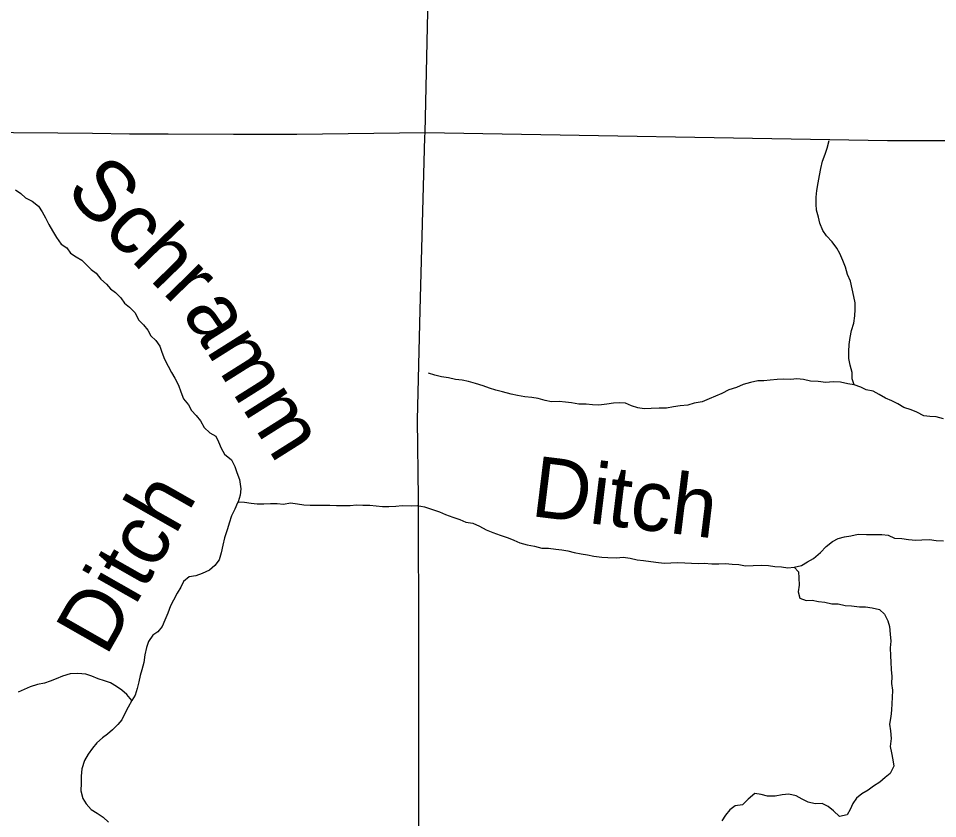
# Model space of a CAD drawing. Extents: x 1857828 to 2277390, y 930619 to 1324581.
# Drawn here: x 2048680 to 2056259, y 1210395 to 1216995 of the extents above; entities that cross this region are included whole.
import ezdxf

# ---------------------------------------------------------------- set-up
doc = ezdxf.new("R2010")
doc.units = 0
for name, color, linetype in [('GM_X_County_Road', 7, 'Continuous'), ('GM_X_Minor_River', 7, 'Continuous'), ('GM_X_Minor_River_Text', 7, 'Continuous')]:
    doc.layers.add(name, color=color, linetype=linetype)

msp = doc.modelspace()

# ---------------------------------------------------------------- linework, layer by layer
at = {"layer": 'GM_X_County_Road'}
for points in [[(2052033.4, 1216053.9), (2052081.4, 1218170.7), (2052124.1, 1220530.3), (2052126.8, 1220631.7), (2052134.8, 1220709.1), (2052153.5, 1220767.9), (2052228.2, 1220904), (2052543.2, 1221491.3), (2052548.6, 1221659.4), (2052615.3, 1223968.4), (2052658, 1225343), (2052682, 1226907.2)], [(2046506.2, 1216127.5), (2048640.4, 1216054.1), (2049006, 1216051.1), (2049291.8, 1216047.4), (2049597.6, 1216044), (2049915.3, 1216042.6), (2050452.9, 1216041), (2050976.4, 1216041.3), (2052033.4, 1216053.9), (2055846.4, 1215989.3), (2056807.6, 1215987.2), (2057087.8, 1215986.6), (2059001.3, 1216013.3), (2059118.3, 1216013.3), (2059283.5, 1216005.2), (2059444.8, 1215973), (2060293.5, 1215682.6), (2060318.6, 1215682.6)], [(2051873.2, 1205339.4), (2051891.9, 1205707.8), (2051932, 1206839.5), (2051972, 1208043.4), (2051982.7, 1209818.5), (2051982.7, 1211799.1), (2051980, 1213035), (2051972, 1213683.6), (2051993.3, 1214588.5), (2052032.3, 1216016.4), (2052033.4, 1216053.9)]]:
    msp.add_lwpolyline(points, dxfattribs=at)
at = {"layer": 'GM_X_Minor_River'}
for points in [[(2056306, 1213693.3), (2056248.1, 1213707.6), (2056194.1, 1213711.9), (2056144.1, 1213718.1), (2056088.2, 1213746.4), (2056040.3, 1213766.7), (2055980.4, 1213785), (2055930.5, 1213815.3), (2055880.6, 1213841.6), (2055828.7, 1213861.9), (2055776.8, 1213892.2), (2055726.9, 1213920.5), (2055671, 1213930.8), (2055625.1, 1213953.1), (2055571.2, 1213973.4), (2055553.4, 1214021.6), (2055553.6, 1214073.7), (2055537.8, 1214133.9), (2055528.1, 1214190.1), (2055526.3, 1214248.2), (2055530.6, 1214304.3), (2055538.8, 1214362.4), (2055549, 1214420.5), (2055567.3, 1214482.6), (2055577.6, 1214540.7), (2055579.8, 1214594.8), (2055580, 1214648.9), (2055568.2, 1214701.1), (2055554.5, 1214765.3), (2055540.8, 1214827.5), (2055517, 1214883.7), (2055499.2, 1214944), (2055477.5, 1214998.2), (2055453.7, 1215056.4), (2055427.9, 1215100.7), (2055388.1, 1215153), (2055342.3, 1215201.3), (2055312.5, 1215245.5), (2055286.8, 1215305.8), (2055277, 1215356), (2055261.2, 1215412.2), (2055257.4, 1215462.3), (2055257.7, 1215520.4), (2055263.9, 1215574.5), (2055274.2, 1215638.6), (2055284.4, 1215700.7), (2055294.7, 1215756.8), (2055308.9, 1215818.9), (2055331.2, 1215874.9), (2055349.4, 1215925), (2055363.6, 1215987)], [(2048657.8, 1215580.9), (2048701.6, 1215550.6), (2048739.5, 1215514.4), (2048793.4, 1215488.1), (2048845.2, 1215445.7), (2048877, 1215399.5), (2048904.8, 1215349.2), (2048932.6, 1215295), (2048960.4, 1215242.7), (2048994.1, 1215188.4), (2049031.9, 1215134.1), (2049079.8, 1215101.8), (2049109.6, 1215057.6), (2049157.5, 1215027.3), (2049203.3, 1215001), (2049243.2, 1214962.8), (2049281, 1214924.5), (2049320.9, 1214894.2), (2049360.7, 1214843.9), (2049406.5, 1214803.6), (2049440.4, 1214765.4), (2049480.2, 1214733.1), (2049526.1, 1214690.8), (2049555.9, 1214646.6), (2049597.7, 1214612.3), (2049643.5, 1214566), (2049669.3, 1214509.8), (2049713.1, 1214467.4), (2049748.9, 1214423.2), (2049772.8, 1214377), (2049812.6, 1214338.7), (2049846.4, 1214292.4), (2049864.2, 1214242.2), (2049885.9, 1214184), (2049915.7, 1214127.7), (2049941.5, 1214075.5), (2049969.3, 1214029.2), (2050001.1, 1213971), (2050020.8, 1213914.8), (2050042.6, 1213856.5), (2050082.4, 1213808.2), (2050108.2, 1213762), (2050146, 1213719.7), (2050181.8, 1213675.4), (2050211.6, 1213621.2), (2050259.4, 1213576.9), (2050307.3, 1213550.6), (2050329.1, 1213502.4), (2050352.9, 1213450.1), (2050380.7, 1213399.9), (2050436.5, 1213353.5), (2050464.3, 1213299.3), (2050482, 1213251.1), (2050503.8, 1213192.9), (2050515.5, 1213114.6), (2050509.3, 1213062.5), (2050493, 1213008.5)], [(2055571.2, 1213973.4), (2055517.2, 1213981.6), (2055459.3, 1213995.9), (2055397.3, 1213998.2), (2055337.3, 1213992.5), (2055275.3, 1214000.8), (2055211.3, 1214003.1), (2055153.3, 1214017.4), (2055097.4, 1214021.7), (2055047.4, 1214017.9), (2054987.4, 1214020.2), (2054935.3, 1214016.4), (2054877.3, 1214012.7), (2054827.3, 1214006.9), (2054775.3, 1214005.1), (2054717.2, 1213991.3), (2054655.2, 1213975.6), (2054601.1, 1213951.8), (2054537, 1213932), (2054478.9, 1213900.2), (2054428.8, 1213878.4), (2054374.7, 1213856.6), (2054316.6, 1213832.8), (2054252.5, 1213821.1), (2054198.4, 1213805.3), (2054136.4, 1213799.6), (2054082.4, 1213791.8), (2054022.3, 1213780.1), (2053962.3, 1213780.3), (2053898.3, 1213778.6), (2053840.3, 1213774.9), (2053788.3, 1213783.1), (2053734.4, 1213799.4), (2053686.5, 1213821.7), (2053636.5, 1213823.9), (2053586.5, 1213822.2), (2053530.5, 1213814.4), (2053466.4, 1213804.7), (2053412.4, 1213806.9), (2053360.5, 1213813.2), (2053300.5, 1213813.5), (2053240.5, 1213823.8), (2053190.5, 1213830), (2053138.6, 1213836.3), (2053076.5, 1213832.5), (2053022.6, 1213844.8), (2052964.7, 1213861.1), (2052912.7, 1213869.4), (2052854.7, 1213873.6), (2052794.8, 1213883.9), (2052742.8, 1213896.2), (2052672.9, 1213914.6), (2052616.9, 1213928.9), (2052565, 1213945.1), (2052511.1, 1213963.4), (2052449.2, 1213983.8), (2052391.2, 1214000.1), (2052339.3, 1214010.3), (2052285.3, 1214016.6), (2052225.4, 1214030.9), (2052167.4, 1214039.2), (2052113.5, 1214053.5), (2052061.5, 1214069.8)], [(2050493, 1213008.5), (2050487, 1212998.5), (2050464.8, 1212946.5), (2050438.5, 1212892.4), (2050418.3, 1212832.4), (2050404.1, 1212784.4), (2050379.8, 1212712.3), (2050365.5, 1212650.2), (2050351.3, 1212586.1), (2050337, 1212530.1), (2050300.8, 1212482.1), (2050254.7, 1212444.3), (2050196.5, 1212416.5), (2050142.5, 1212396.7), (2050088.4, 1212388.9), (2050042.3, 1212351), (2050020.1, 1212305), (2049989.9, 1212255), (2049959.6, 1212197), (2049935.4, 1212149), (2049911.2, 1212089), (2049888.9, 1212033), (2049866.7, 1211981), (2049830.5, 1211937), (2049788.4, 1211909.2), (2049752.2, 1211857.2), (2049736, 1211807.2), (2049723.7, 1211745.1), (2049715.5, 1211683), (2049699.2, 1211622.9), (2049685, 1211574.9), (2049672.8, 1211522.8), (2049658.6, 1211468.7), (2049642.3, 1211412.7), (2049616.1, 1211368.7), (2049585.9, 1211314.7), (2049561.7, 1211268.7), (2049533.5, 1211210.7), (2049499.3, 1211170.8), (2049457.1, 1211126.9), (2049415, 1211091), (2049372.9, 1211061.1), (2049326.7, 1211019.2), (2049292.5, 1210975.3), (2049256.3, 1210927.3), (2049224.1, 1210873.4), (2049203.8, 1210805.3), (2049197.5, 1210745.2), (2049197.3, 1210687.1), (2049195, 1210624.9), (2049210.8, 1210560.7), (2049238.6, 1210516.5), (2049280.4, 1210470.2), (2049330.3, 1210439.9), (2049380.1, 1210407.6), (2049422, 1210365.3)], [(2050493, 1213008.5), (2050545, 1213004.2), (2050599, 1212998), (2050649, 1212991.7), (2050705, 1212991.5), (2050759, 1212993.2), (2050813, 1212993), (2050867, 1212988.7), (2050925, 1213000.5), (2050981, 1212992.2), (2051034.9, 1212981.9), (2051084.9, 1212979.7), (2051144.9, 1212979.4), (2051196.9, 1212979.2), (2051248.9, 1212980.9), (2051302.9, 1212976.7), (2051362.9, 1212976.4), (2051414.9, 1212978.2), (2051468.9, 1212981.9), (2051518.9, 1212979.7), (2051576.9, 1212981.4), (2051628.9, 1212975.2), (2051680.9, 1212968.9), (2051734.9, 1212968.7), (2051792.9, 1212972.4), (2051844.9, 1212978.2), (2051918.9, 1212975.9), (2051968.9, 1212977.6), (2052028.9, 1212967.3), (2052086.8, 1212947), (2052152.7, 1212924.7), (2052200.6, 1212902.4), (2052262.5, 1212880.1), (2052318.5, 1212861.8), (2052368.4, 1212839.5), (2052426.3, 1212831.2), (2052482.2, 1212806.9), (2052538.1, 1212776.6), (2052592, 1212754.2), (2052651.9, 1212733.9), (2052717.8, 1212711.6), (2052765.8, 1212691.3), (2052815.7, 1212671), (2052875.6, 1212652.7), (2052935.5, 1212642.4), (2052995.5, 1212626.1), (2053051.5, 1212625.8), (2053111.4, 1212617.6), (2053161.4, 1212613.3), (2053211.4, 1212603.1), (2053263.3, 1212590.8), (2053321.3, 1212578.5), (2053373.2, 1212570.2), (2053425.2, 1212560), (2053489.2, 1212551.6), (2053541.2, 1212549.4), (2053611.2, 1212547.1), (2053665.2, 1212550.8), (2053723.1, 1212542.6), (2053783.1, 1212530.3), (2053835.1, 1212524), (2053895, 1212515.7), (2053957, 1212507.4), (2054007, 1212503.2), (2054059, 1212504.9), (2054113, 1212508.7), (2054175, 1212504.4), (2054229, 1212502.1), (2054285, 1212499.9), (2054335, 1212501.6), (2054397, 1212497.3), (2054455, 1212497.1), (2054511, 1212498.8), (2054564.9, 1212492.6), (2054618.9, 1212490.3), (2054674.9, 1212480), (2054738.9, 1212481.7), (2054804.9, 1212485.4), (2054864.9, 1212483.2), (2054916.9, 1212474.9), (2054972.9, 1212470.6), (2055024.8, 1212464.4), (2055074.8, 1212468.2), (2055136.9, 1212481.9), (2055187, 1212511.7), (2055235.2, 1212541.6), (2055293.4, 1212591.4), (2055339.6, 1212639.3), (2055391.7, 1212681.2), (2055437.8, 1212705), (2055491.9, 1212718.8), (2055542, 1212728.6), (2055604, 1212742.3), (2055672, 1212738), (2055730, 1212739.8), (2055798, 1212739.4), (2055850, 1212733.2), (2055903.9, 1212708.9), (2055963.8, 1212704.6), (2056019.8, 1212698.3), (2056077.8, 1212692.1)], [(2056077.8, 1212692.1), (2056129.8, 1212693.8), (2056191.8, 1212697.5), (2056245.8, 1212689.3), (2056307.8, 1212685)], [(2055074.8, 1212468.2), (2055112.7, 1212431.9), (2055114.5, 1212381.8), (2055118.2, 1212321.6), (2055110, 1212265.5), (2055123.8, 1212213.3), (2055175.7, 1212195.1), (2055225.7, 1212196.8), (2055277.7, 1212186.6), (2055327.6, 1212180.3), (2055385.6, 1212166), (2055437.6, 1212167.8), (2055497.5, 1212153.5), (2055549.5, 1212149.2), (2055613.5, 1212142.9), (2055663.5, 1212140.7), (2055719.5, 1212134.4), (2055779.4, 1212120.1), (2055821.2, 1212081.8), (2055847, 1212027.6), (2055860.8, 1211979.4), (2055868.6, 1211917.2), (2055872.3, 1211859.1), (2055868.1, 1211802.9), (2055869.8, 1211738.8), (2055873.6, 1211686.7), (2055875.3, 1211624.5), (2055881.1, 1211568.4), (2055878.8, 1211510.2), (2055886.6, 1211454.1), (2055884.4, 1211393.9), (2055880.1, 1211343.8), (2055879.9, 1211289.7), (2055871.7, 1211237.6), (2055863.4, 1211175.5), (2055869.2, 1211119.4), (2055874.9, 1211057.2), (2055868.7, 1210989.1), (2055878.4, 1210936.9), (2055890.2, 1210878.7), (2055898, 1210826.6), (2055867.7, 1210766.6), (2055827.6, 1210734.7), (2055781.4, 1210694.8), (2055729.3, 1210663), (2055685.2, 1210629.1), (2055635, 1210599.3), (2055590.9, 1210563.4), (2055560.7, 1210519.4), (2055536.5, 1210471.4), (2055512.3, 1210425.4), (2055450.2, 1210411.7), (2055400.4, 1210460), (2055356.6, 1210496.3), (2055306.7, 1210518.6), (2055248.7, 1210516.9), (2055190.7, 1210531.1), (2055140.8, 1210555.4), (2055092.9, 1210583.7), (2055031, 1210596), (2054977, 1210592.3), (2054918.9, 1210580.5), (2054856.9, 1210580.8), (2054803, 1210593.1), (2054753, 1210603.3), (2054696.8, 1210555.5), (2054650.6, 1210509.6), (2054588.6, 1210501.9), (2054544.5, 1210468), (2054510.3, 1210424.1), (2054480.1, 1210378.1)], [(2049616.1, 1211368.7), (2049574.4, 1211419), (2049532.5, 1211455.3), (2049490.6, 1211485.6), (2049438.7, 1211513.8), (2049390.8, 1211532.1), (2049336.9, 1211548.4), (2049285, 1211570.7), (2049237.1, 1211586.9), (2049171.1, 1211591.2), (2049107.1, 1211589.6), (2049045, 1211569.8), (2048992.9, 1211548), (2048942.8, 1211530.2), (2048894.7, 1211512.3), (2048836.7, 1211500.6), (2048778.6, 1211482.8), (2048728.5, 1211459), (2048678.4, 1211437.2)]]:
    msp.add_lwpolyline(points, dxfattribs=at)

# ---------------------------------------------------------------- texts
at = {"layer": 'GM_X_Minor_River_Text'}
for s, height, rotation, p in [('Schr', 500.27, 314.20243, (2049056.4, 1215560.9)), ('amm', 500.27, 302.20256, (2050024.6, 1214570.9)), ('Ditch', 500.26, 353.00743, (2052895.9, 1212891.8)), ('Ditch', 500.27, 60.35344, (2049403.9, 1211725.1))]:
    msp.add_text(s, height=height, rotation=rotation, dxfattribs=at).set_placement(p)

doc.saveas('drawing.dxf')
